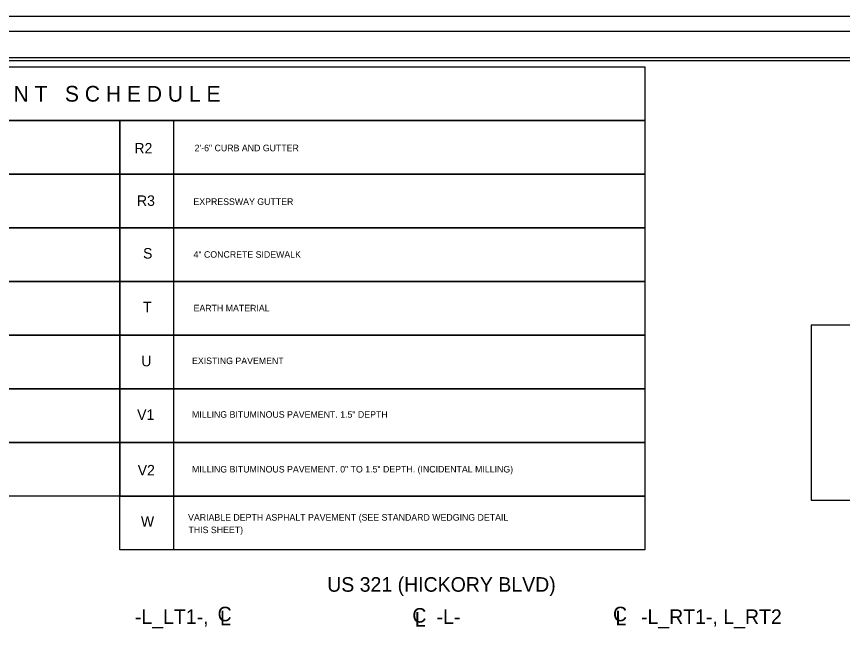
# Model space of a CAD drawing. Extents: x 2294455 to 2294842, y 719496 to 719941.
# Drawn here: x 2294561.3 to 2294702.9, y 719613.8 to 719718.8 of the extents above; entities that cross this region are included whole.
import ezdxf

# ---------------------------------------------------------------- set-up
doc = ezdxf.new("R2010")
doc.units = 0
for name, color, linetype in [('Old_Level_2', 7, 'Continuous'), ('Old_Level_3', 7, 'Continuous'), ('Prop Pavement Schedule Description CELL', 7, 'Continuous'), ('Sheet Cutting Line CELL', 7, 'Continuous'), ('Sheet Plan CELL', 7, 'Continuous'), ('Sheet Plot Border Inside CELL', 7, 'Continuous'), ('Sheet Plot Border Outside CELL', 7, 'Continuous'), ('Sheet Typical CELL', 7, 'Continuous')]:
    doc.layers.add(name, color=color, linetype=linetype)

msp = doc.modelspace()

# ---------------------------------------------------------------- linework, layer by layer
at = {"layer": 'Prop Pavement Schedule Description CELL'}
for p, q in [((2294579.01, 719654.89), (2294579.01, 719664.09)), ((2294579.01, 719664.09), (2294669.01, 719664.09)), ((2294588.22, 719654.89), (2294588.22, 719664.09)), ((2294669.01, 719664.09), (2294669.01, 719654.89)), ((2294588.22, 719654.89), (2294579.01, 719654.89)), ((2294669.01, 719654.89), (2294588.22, 719654.89)), ((2294579.01, 719636.48), (2294579.01, 719645.69)), ((2294579.01, 719645.69), (2294669.02, 719645.69)), ((2294588.22, 719636.48), (2294588.22, 719645.69)), ((2294669.02, 719645.69), (2294669.02, 719636.48)), ((2294588.22, 719636.48), (2294579.01, 719636.48)), ((2294669.02, 719636.48), (2294588.22, 719636.48))]:
    msp.add_line(p, q, dxfattribs=at)
msp.add_lwpolyline([(2294489.01, 719710.12), (2294669.02, 719710.12), (2294669.02, 719700.91), (2294489.01, 719700.91)], close=True, dxfattribs=at)
for points in [[(2294498.22, 719691.71), (2294489.01, 719691.71), (2294489.01, 719700.91), (2294579.01, 719700.91), (2294579.01, 719691.71), (2294498.22, 719691.71), (2294498.22, 719700.91)], [(2294588.22, 719691.71), (2294579.01, 719691.71), (2294579.01, 719700.91), (2294669.02, 719700.91), (2294669.02, 719691.71), (2294588.22, 719691.71), (2294588.22, 719700.91)], [(2294498.22, 719682.5), (2294489.01, 719682.5), (2294489.01, 719691.71), (2294579.01, 719691.71), (2294579.01, 719682.5), (2294498.22, 719682.5), (2294498.22, 719691.71)], [(2294588.22, 719682.5), (2294579.01, 719682.5), (2294579.01, 719691.71), (2294669.02, 719691.71), (2294669.02, 719682.5), (2294588.22, 719682.5), (2294588.22, 719691.71)], [(2294588.22, 719682.5), (2294579.01, 719682.5), (2294579.01, 719691.71), (2294669.01, 719691.71), (2294669.01, 719682.5), (2294588.22, 719682.5), (2294588.22, 719691.71)], [(2294588.22, 719682.5), (2294579.01, 719682.5), (2294579.01, 719691.71), (2294669.01, 719691.71), (2294669.01, 719682.5), (2294588.22, 719682.5), (2294588.22, 719691.71)], [(2294498.22, 719673.3), (2294489.01, 719673.3), (2294489.01, 719682.5), (2294579.01, 719682.5), (2294579.01, 719673.3), (2294498.22, 719673.3), (2294498.22, 719682.5)], [(2294588.22, 719673.3), (2294579.01, 719673.3), (2294579.01, 719682.5), (2294669.01, 719682.5), (2294669.01, 719673.3), (2294588.22, 719673.3), (2294588.22, 719682.5)], [(2294498.22, 719664.09), (2294489.01, 719664.09), (2294489.01, 719673.3), (2294579.01, 719673.3), (2294579.01, 719664.09), (2294498.22, 719664.09), (2294498.22, 719673.3)], [(2294588.22, 719664.09), (2294579.01, 719664.09), (2294579.01, 719673.3), (2294669.01, 719673.3), (2294669.01, 719664.09), (2294588.22, 719664.09), (2294588.22, 719673.3)], [(2294498.22, 719654.89), (2294489.01, 719654.89), (2294489.01, 719664.09), (2294579.01, 719664.09), (2294579.01, 719654.89), (2294498.22, 719654.89), (2294498.22, 719664.09)], [(2294498.22, 719645.69), (2294489.01, 719645.69), (2294489.01, 719654.89), (2294579.01, 719654.89), (2294579.01, 719645.69), (2294498.22, 719645.69), (2294498.22, 719654.89)], [(2294588.22, 719645.69), (2294579.01, 719645.69), (2294579.01, 719654.89), (2294669.01, 719654.89), (2294669.01, 719645.69), (2294588.22, 719645.69), (2294588.22, 719654.89)], [(2294498.22, 719636.48), (2294489.01, 719636.48), (2294489.01, 719645.69), (2294579.01, 719645.69), (2294579.01, 719636.48), (2294498.22, 719636.48), (2294498.22, 719645.69)], [(2294588.22, 719627.28), (2294579.01, 719627.28), (2294579.01, 719636.48), (2294669.02, 719636.48), (2294669.02, 719627.28), (2294588.22, 719627.28), (2294588.22, 719636.48)]]:
    msp.add_lwpolyline(points, dxfattribs=at)
at = {"layer": 'Sheet Cutting Line CELL'}
msp.add_line((2294791.32, 719716.17), (2294454.52, 719716.17), dxfattribs=at)
at = {"layer": 'Sheet Plan CELL'}
msp.add_lwpolyline([(2294697.55, 719665.81), (2294697.55, 719635.81), (2294769.86, 719635.81), (2294769.86, 719665.81)], close=True, dxfattribs=at)
at = {"layer": 'Sheet Plot Border Inside CELL'}
msp.add_lwpolyline([(2294790.42, 719711.68), (2294457.12, 719711.68), (2294457.12, 719500.66), (2294790.42, 719500.66)], close=True, dxfattribs=at)
at = {"layer": 'Sheet Plot Border Outside CELL'}
for points in [[(2294793.79, 719718.76), (2294456.99, 719718.76), (2294456.99, 719498.76), (2294793.79, 719498.76)], [(2294791.32, 719716.17), (2294454.52, 719716.17), (2294454.52, 719496.17), (2294791.32, 719496.17)]]:
    msp.add_lwpolyline(points, close=True, dxfattribs=at)
at = {"layer": 'Sheet Typical CELL'}
msp.add_lwpolyline([(2294787.92, 719711.17), (2294487.92, 719711.17), (2294487.92, 719501.17), (2294787.92, 719501.17)], close=True, dxfattribs=at)

# ---------------------------------------------------------------- texts
at = {"layer": 'Old_Level_2'}
for s, rotation, p in [('C', 360, (2294595.75, 719615.04)), ('C', 360, (2294663.57, 719615.04)), ('L', 359.9469, (2294596.17, 719614.34)), ('C', 360, (2294629.15, 719614.81)), ('L', 359.9469, (2294629.58, 719614.11)), ('L', 359.9469, (2294663.99, 719614.34))]:
    msp.add_text(s, height=2.5, rotation=rotation, dxfattribs=at).set_placement(p)
at = {"layer": 'Old_Level_3'}
for s, p in [('US 321 (HICKORY BLVD)', (2294614.55, 719620.11)), ('-L_LT1-,', (2294581.57, 719614.58)), ('-L-', (2294633.31, 719614.58)), ('-L_RT1-, L_RT2', (2294668.37, 719614.58))]:
    msp.add_text(s, height=2.5, rotation=0, dxfattribs=at).set_placement(p)
at = {"layer": 'Prop Pavement Schedule Description CELL'}
for s, height, p in [('F I N A L   P A V E M E N T   S C H E D U L E', 2.7, (2294522.42, 719704.16)), ('2\'-6" CURB AND GUTTER', 1.125, (2294591.82, 719695.65)), ('EXPRESSWAY GUTTER', 1.125, (2294591.61, 719686.45)), ('S', 1.8, (2294582.97, 719677.25)), ('4" CONCRETE SIDEWALK', 1.125, (2294591.63, 719677.39)), ('T', 1.8, (2294582.97, 719668.04)), ('EARTH MATERIAL', 1.125, (2294591.63, 719668.19)), ('U', 1.8, (2294582.67, 719658.77)), ('EXISTING PAVEMENT', 1.125, (2294591.37, 719659.15)), ('V1', 1.8, (2294581.95, 719649.57)), ('MILLING BITUMINOUS PAVEMENT. 1.5" DEPTH', 1.125, (2294591.37, 719649.95)), ('V2', 1.8, (2294582.05, 719640.06)), ('MILLING BITUMINOUS PAVEMENT. 0" TO 1.5" DEPTH. (INCIDENTAL MILLING)', 1.125, (2294591.37, 719640.56)), ('VARIABLE DEPTH ASPHALT PAVEMENT (SEE STANDARD WEDGING DETAIL', 1.125, (2294590.69, 719632.3)), ('W', 1.8, (2294582.6, 719631.27)), ('THIS SHEET)', 1.125, (2294590.76, 719630.16))]:
    msp.add_text(s, height=height, rotation=0, dxfattribs=at).set_placement(p)
for s, p in [('R2', (2294581.49, 719695.27)), ('R3', (2294581.92, 719686.28))]:
    msp.add_text(s, height=1.8, dxfattribs=at).set_placement(p)

doc.saveas('drawing.dxf')
